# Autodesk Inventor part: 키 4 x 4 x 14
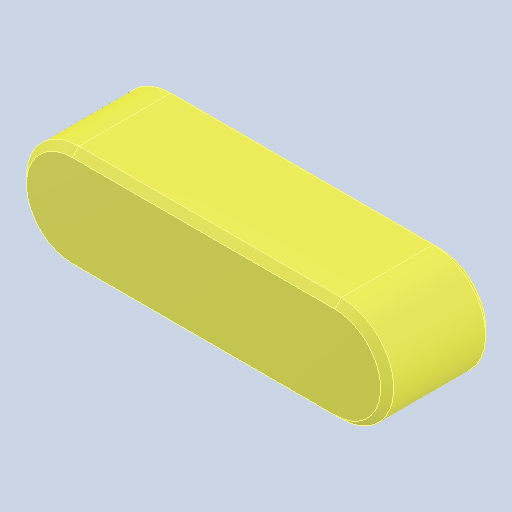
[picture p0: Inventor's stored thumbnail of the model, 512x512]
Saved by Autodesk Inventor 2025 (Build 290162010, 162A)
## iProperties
Created: 2024-07
Part Number: 키 4 x 4 x 14
Material: 강철, 연강
Description: 키 및 해당 키홈
Document SubType Name: Modeling
Designer: 학생
Density: 7.85 g/cm^3
Appearance: 기본값
Author: jhkim
Sending System: Autodesk Inventor 2025
Preprocessor: ST-DEVELOPER v20
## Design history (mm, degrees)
feature "Solid1"
node "솔리드1"
